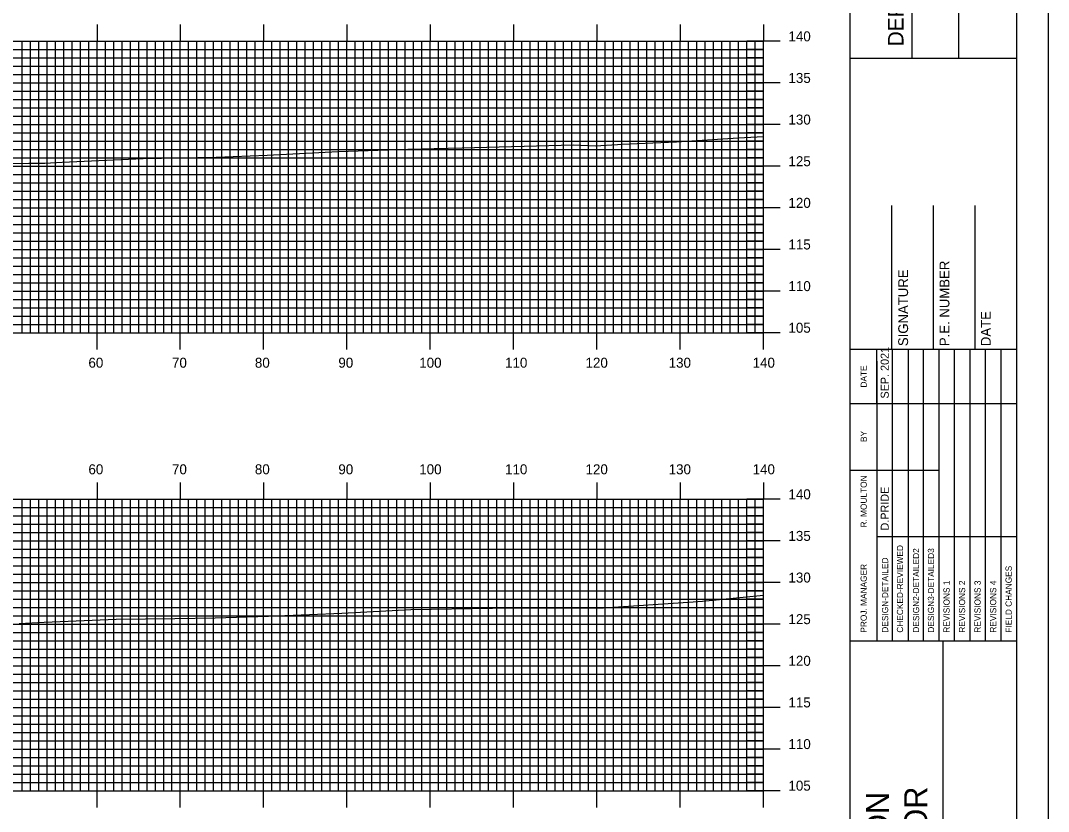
# Model space of a CAD drawing. Extents: x 852147 to 852490, y 364661 to 364881.
# Drawn here: x 852363.6 to 852487, y 364736.9 to 364831.9 of the extents above; entities that cross this region are included whole.
import ezdxf

# ---------------------------------------------------------------- set-up
doc = ezdxf.new("R2010")
doc.units = 0
for name, color, linetype in [('BORDER', 7, 'Continuous'), ('H_V ANNOTATION', 7, 'Continuous'), ('MAJOR', 7, 'Continuous'), ('MINOR', 7, 'Continuous'), ('PLOT BOUNDARY', 7, 'Continuous'), ('S_Roadway_Centerline', 7, 'Continuous')]:
    doc.layers.add(name, color=color, linetype=linetype)

msp = doc.modelspace()

# ---------------------------------------------------------------- linework, layer by layer
at = {"layer": 'BORDER'}
for p, q in [((852463.16, 364667.37), (852463.16, 364877.37)), ((852470.61, 364827.36), (852470.61, 364877.36)), ((852476.2, 364827.36), (852476.2, 364877.36)), ((852463.16, 364827.36), (852483.16, 364827.36)), ((852468.16, 364792.38), (852468.16, 364809.67)), ((852473.16, 364792.38), (852473.16, 364809.67)), ((852478.16, 364792.38), (852478.16, 364809.67)), ((852463.16, 364792.38), (852483.16, 364792.38)), ((852463.16, 364757.38), (852483.16, 364757.38)), ((852474.34, 364687.38), (852474.34, 364757.38))]:
    msp.add_line(p, q, dxfattribs=at)
msp.add_lwpolyline([(852163.16, 364667.37), (852483.16, 364667.37), (852483.16, 364877.37), (852163.16, 364877.37)], close=True, dxfattribs=at)
for points in [[(852466.38, 364785.88), (852466.38, 364792.38)], [(852468.25, 364757.38), (852468.25, 364792.38)], [(852470.11, 364792.38), (852470.11, 364757.38)], [(852471.98, 364757.38), (852471.98, 364792.38)], [(852473.84, 364757.38), (852473.84, 364792.38)], [(852475.7, 364757.38), (852475.7, 364792.38)], [(852477.57, 364757.38), (852477.57, 364792.38)], [(852479.43, 364757.38), (852479.43, 364792.38)], [(852481.29, 364757.38), (852481.29, 364792.38)], [(852466.39, 364757.38), (852466.39, 364790.96)], [(852463.16, 364785.88), (852483.16, 364785.88)], [(852463.16, 364777.88), (852466.39, 364777.88)], [(852466.38, 364777.88), (852473.84, 364777.88)], [(852466.38, 364769.88), (852483.16, 364769.88)]]:
    msp.add_lwpolyline(points, dxfattribs=at)
at = {"layer": 'MAJOR'}
for p, q in [((852372.76, 364831.37), (852372.76, 364829.37)), ((852382.76, 364831.37), (852382.76, 364829.37)), ((852392.76, 364831.37), (852392.76, 364829.37)), ((852402.76, 364831.37), (852402.76, 364829.37)), ((852412.76, 364831.37), (852412.76, 364829.37)), ((852422.76, 364831.37), (852422.76, 364829.37)), ((852432.76, 364831.37), (852432.76, 364829.37)), ((852442.76, 364831.37), (852442.76, 364829.37)), ((852452.76, 364831.37), (852452.76, 364829.37)), ((852172.76, 364829.37), (852452.76, 364829.37)), ((852172.76, 364829.37), (852452.76, 364829.37)), ((852372.76, 364794.37), (852372.76, 364829.37)), ((852382.76, 364794.37), (852382.76, 364829.37)), ((852392.76, 364794.37), (852392.76, 364829.37)), ((852402.76, 364794.37), (852402.76, 364829.37)), ((852412.76, 364794.37), (852412.76, 364829.37)), ((852422.76, 364794.37), (852422.76, 364829.37)), ((852432.76, 364794.37), (852432.76, 364829.37)), ((852442.76, 364794.37), (852442.76, 364829.37)), ((852454.76, 364829.37), (852450.75, 364829.37)), ((852452.76, 364794.37), (852452.76, 364829.37)), ((852452.76, 364794.37), (852452.76, 364829.37)), ((852172.76, 364824.37), (852452.76, 364824.37)), ((852454.76, 364824.37), (852450.75, 364824.37)), ((852172.76, 364819.37), (852452.76, 364819.37)), ((852454.76, 364819.37), (852450.75, 364819.37)), ((852172.76, 364814.37), (852452.76, 364814.37)), ((852454.76, 364814.37), (852450.75, 364814.37)), ((852172.76, 364809.37), (852452.76, 364809.37)), ((852454.76, 364809.37), (852450.75, 364809.37)), ((852172.76, 364804.37), (852452.76, 364804.37)), ((852454.76, 364804.37), (852450.75, 364804.37)), ((852172.76, 364799.37), (852452.76, 364799.37)), ((852454.76, 364799.37), (852450.75, 364799.37)), ((852172.76, 364794.37), (852452.76, 364794.37)), ((852172.76, 364794.37), (852452.76, 364794.37)), ((852372.76, 364792.37), (852372.76, 364794.37)), ((852382.76, 364792.37), (852382.76, 364794.37)), ((852392.76, 364792.37), (852392.76, 364794.37)), ((852402.76, 364792.37), (852402.76, 364794.37)), ((852412.76, 364792.37), (852412.76, 364794.37)), ((852422.76, 364792.37), (852422.76, 364794.37)), ((852432.76, 364792.37), (852432.76, 364794.37)), ((852442.76, 364792.37), (852442.76, 364794.37)), ((852454.76, 364794.37), (852450.75, 364794.37)), ((852452.76, 364792.37), (852452.76, 364794.37)), ((852372.76, 364776.37), (852372.76, 364774.37)), ((852382.76, 364776.37), (852382.76, 364774.37)), ((852392.76, 364776.37), (852392.76, 364774.37)), ((852402.76, 364776.37), (852402.76, 364774.37)), ((852412.76, 364776.37), (852412.76, 364774.37)), ((852422.76, 364776.37), (852422.76, 364774.37)), ((852432.76, 364776.37), (852432.76, 364774.37)), ((852442.76, 364776.37), (852442.76, 364774.37)), ((852452.76, 364776.37), (852452.76, 364774.37)), ((852172.76, 364774.37), (852452.76, 364774.37)), ((852172.76, 364774.37), (852452.76, 364774.37)), ((852372.76, 364739.37), (852372.76, 364774.37)), ((852382.76, 364739.37), (852382.76, 364774.37)), ((852392.76, 364739.37), (852392.76, 364774.37)), ((852402.76, 364739.37), (852402.76, 364774.37)), ((852412.76, 364739.37), (852412.76, 364774.37)), ((852422.76, 364739.37), (852422.76, 364774.37)), ((852432.76, 364739.37), (852432.76, 364774.37)), ((852442.76, 364739.37), (852442.76, 364774.37)), ((852454.76, 364774.37), (852450.75, 364774.37)), ((852452.76, 364739.37), (852452.76, 364774.37)), ((852452.76, 364739.37), (852452.76, 364774.37)), ((852172.76, 364769.37), (852452.76, 364769.37)), ((852454.76, 364769.37), (852450.75, 364769.37)), ((852172.76, 364764.37), (852452.76, 364764.37)), ((852454.76, 364764.37), (852450.75, 364764.37)), ((852172.76, 364759.37), (852452.76, 364759.37)), ((852454.76, 364759.37), (852450.75, 364759.37)), ((852172.76, 364754.37), (852452.76, 364754.37)), ((852454.76, 364754.37), (852450.75, 364754.37)), ((852172.76, 364749.37), (852452.76, 364749.37)), ((852454.76, 364749.37), (852450.75, 364749.37)), ((852172.76, 364744.37), (852452.76, 364744.37)), ((852454.76, 364744.37), (852450.75, 364744.37)), ((852172.76, 364739.37), (852452.76, 364739.37)), ((852172.76, 364739.37), (852452.76, 364739.37)), ((852372.76, 364737.37), (852372.76, 364739.37)), ((852382.76, 364737.37), (852382.76, 364739.37)), ((852392.76, 364737.37), (852392.76, 364739.37)), ((852402.76, 364737.37), (852402.76, 364739.37)), ((852412.76, 364737.37), (852412.76, 364739.37)), ((852422.76, 364737.37), (852422.76, 364739.37)), ((852432.76, 364737.37), (852432.76, 364739.37)), ((852442.76, 364737.37), (852442.76, 364739.37)), ((852454.76, 364739.37), (852450.75, 364739.37)), ((852452.76, 364737.37), (852452.76, 364739.37))]:
    msp.add_line(p, q, dxfattribs=at)
at = {"layer": 'MINOR'}
for p, q in [((852363.76, 364794.37), (852363.76, 364829.37)), ((852364.76, 364794.37), (852364.76, 364829.37)), ((852365.76, 364794.37), (852365.76, 364829.37)), ((852366.76, 364794.37), (852366.76, 364829.37)), ((852367.76, 364794.37), (852367.76, 364829.37)), ((852368.76, 364794.37), (852368.76, 364829.37)), ((852369.76, 364794.37), (852369.76, 364829.37)), ((852370.76, 364794.37), (852370.76, 364829.37)), ((852371.76, 364794.37), (852371.76, 364829.37)), ((852373.76, 364794.37), (852373.76, 364829.37)), ((852374.76, 364794.37), (852374.76, 364829.37)), ((852375.76, 364794.37), (852375.76, 364829.37)), ((852376.76, 364794.37), (852376.76, 364829.37)), ((852377.76, 364794.37), (852377.76, 364829.37)), ((852378.76, 364794.37), (852378.76, 364829.37)), ((852379.76, 364794.37), (852379.76, 364829.37)), ((852380.76, 364794.37), (852380.76, 364829.37)), ((852381.76, 364794.37), (852381.76, 364829.37)), ((852383.76, 364794.37), (852383.76, 364829.37)), ((852384.76, 364794.37), (852384.76, 364829.37)), ((852385.76, 364794.37), (852385.76, 364829.37)), ((852386.76, 364794.37), (852386.76, 364829.37)), ((852387.76, 364794.37), (852387.76, 364829.37)), ((852388.76, 364794.37), (852388.76, 364829.37)), ((852389.76, 364794.37), (852389.76, 364829.37)), ((852390.76, 364794.37), (852390.76, 364829.37)), ((852391.76, 364794.37), (852391.76, 364829.37)), ((852393.76, 364794.37), (852393.76, 364829.37)), ((852394.76, 364794.37), (852394.76, 364829.37)), ((852395.76, 364794.37), (852395.76, 364829.37)), ((852396.76, 364794.37), (852396.76, 364829.37)), ((852397.76, 364794.37), (852397.76, 364829.37)), ((852398.76, 364794.37), (852398.76, 364829.37)), ((852399.76, 364794.37), (852399.76, 364829.37)), ((852400.76, 364794.37), (852400.76, 364829.37)), ((852401.76, 364794.37), (852401.76, 364829.37)), ((852403.76, 364794.37), (852403.76, 364829.37)), ((852404.76, 364794.37), (852404.76, 364829.37)), ((852405.76, 364794.37), (852405.76, 364829.37)), ((852406.76, 364794.37), (852406.76, 364829.37)), ((852407.76, 364794.37), (852407.76, 364829.37)), ((852408.76, 364794.37), (852408.76, 364829.37)), ((852409.76, 364794.37), (852409.76, 364829.37)), ((852410.76, 364794.37), (852410.76, 364829.37)), ((852411.76, 364794.37), (852411.76, 364829.37)), ((852413.76, 364794.37), (852413.76, 364829.37)), ((852414.76, 364794.37), (852414.76, 364829.37)), ((852415.76, 364794.37), (852415.76, 364829.37)), ((852416.76, 364794.37), (852416.76, 364829.37)), ((852417.76, 364794.37), (852417.76, 364829.37)), ((852418.76, 364794.37), (852418.76, 364829.37)), ((852419.76, 364794.37), (852419.76, 364829.37)), ((852420.76, 364794.37), (852420.76, 364829.37)), ((852421.76, 364794.37), (852421.76, 364829.37)), ((852423.76, 364794.37), (852423.76, 364829.37)), ((852424.76, 364794.37), (852424.76, 364829.37)), ((852425.76, 364794.37), (852425.76, 364829.37)), ((852426.76, 364794.37), (852426.76, 364829.37)), ((852427.76, 364794.37), (852427.76, 364829.37)), ((852428.76, 364794.37), (852428.76, 364829.37)), ((852429.76, 364794.37), (852429.76, 364829.37)), ((852430.76, 364794.37), (852430.76, 364829.37)), ((852431.76, 364794.37), (852431.76, 364829.37)), ((852433.76, 364794.37), (852433.76, 364829.37)), ((852434.76, 364794.37), (852434.76, 364829.37)), ((852435.76, 364794.37), (852435.76, 364829.37)), ((852436.76, 364794.37), (852436.76, 364829.37)), ((852437.76, 364794.37), (852437.76, 364829.37)), ((852438.76, 364794.37), (852438.76, 364829.37)), ((852439.76, 364794.37), (852439.76, 364829.37)), ((852440.76, 364794.37), (852440.76, 364829.37)), ((852441.76, 364794.37), (852441.76, 364829.37)), ((852443.76, 364794.37), (852443.76, 364829.37)), ((852444.76, 364794.37), (852444.76, 364829.37)), ((852445.76, 364794.37), (852445.76, 364829.37)), ((852446.76, 364794.37), (852446.76, 364829.37)), ((852447.76, 364794.37), (852447.76, 364829.37)), ((852448.76, 364794.37), (852448.76, 364829.37)), ((852449.76, 364794.37), (852449.76, 364829.37)), ((852450.76, 364794.37), (852450.76, 364829.37)), ((852451.76, 364794.37), (852451.76, 364829.37)), ((852172.76, 364828.37), (852452.76, 364828.37)), ((852172.76, 364827.37), (852452.76, 364827.37)), ((852452.76, 364828.37), (852450.75, 364828.37)), ((852452.76, 364827.37), (852450.75, 364827.37)), ((852172.76, 364826.37), (852452.76, 364826.37)), ((852452.76, 364826.37), (852450.75, 364826.37)), ((852172.76, 364825.37), (852452.76, 364825.37)), ((852452.76, 364825.37), (852450.75, 364825.37)), ((852172.76, 364823.37), (852452.76, 364823.37)), ((852452.76, 364823.37), (852450.75, 364823.37)), ((852172.76, 364822.37), (852452.76, 364822.37)), ((852172.76, 364821.37), (852452.76, 364821.37)), ((852452.76, 364822.37), (852450.75, 364822.37)), ((852452.76, 364821.37), (852450.75, 364821.37)), ((852172.76, 364820.37), (852452.76, 364820.37)), ((852452.76, 364820.37), (852450.75, 364820.37)), ((852172.76, 364818.37), (852452.76, 364818.37)), ((852452.76, 364818.37), (852450.75, 364818.37)), ((852172.76, 364817.37), (852452.76, 364817.37)), ((852172.76, 364816.37), (852452.76, 364816.37)), ((852452.76, 364817.37), (852450.75, 364817.37)), ((852452.76, 364816.37), (852450.75, 364816.37)), ((852172.76, 364815.37), (852452.76, 364815.37)), ((852452.76, 364815.37), (852450.75, 364815.37)), ((852172.76, 364813.37), (852452.76, 364813.37)), ((852452.76, 364813.37), (852450.75, 364813.37)), ((852172.76, 364812.37), (852452.76, 364812.37)), ((852172.76, 364811.37), (852452.76, 364811.37)), ((852452.76, 364812.37), (852450.75, 364812.37)), ((852452.76, 364811.37), (852450.75, 364811.37)), ((852172.76, 364810.37), (852452.76, 364810.37)), ((852452.76, 364810.37), (852450.75, 364810.37)), ((852172.76, 364808.37), (852452.76, 364808.37)), ((852452.76, 364808.37), (852450.75, 364808.37)), ((852172.76, 364807.37), (852452.76, 364807.37)), ((852452.76, 364807.37), (852450.75, 364807.37)), ((852172.76, 364806.37), (852452.76, 364806.37)), ((852172.76, 364805.37), (852452.76, 364805.37)), ((852452.76, 364806.37), (852450.75, 364806.37)), ((852452.76, 364805.37), (852450.75, 364805.37)), ((852172.76, 364803.37), (852452.76, 364803.37)), ((852452.76, 364803.37), (852450.75, 364803.37)), ((852172.76, 364802.37), (852452.76, 364802.37)), ((852452.76, 364802.37), (852450.75, 364802.37)), ((852172.76, 364801.37), (852452.76, 364801.37)), ((852172.76, 364800.37), (852452.76, 364800.37)), ((852452.76, 364801.37), (852450.75, 364801.37)), ((852452.76, 364800.37), (852450.75, 364800.37)), ((852172.76, 364798.37), (852452.76, 364798.37)), ((852452.76, 364798.37), (852450.75, 364798.37)), ((852172.76, 364797.37), (852452.76, 364797.37)), ((852452.76, 364797.37), (852450.75, 364797.37)), ((852172.76, 364796.37), (852452.76, 364796.37)), ((852172.76, 364795.37), (852452.76, 364795.37)), ((852452.76, 364796.37), (852450.75, 364796.37)), ((852452.76, 364795.37), (852450.75, 364795.37)), ((852363.76, 364739.37), (852363.76, 364774.37)), ((852364.76, 364739.37), (852364.76, 364774.37)), ((852365.76, 364739.37), (852365.76, 364774.37)), ((852366.76, 364739.37), (852366.76, 364774.37)), ((852367.76, 364739.37), (852367.76, 364774.37)), ((852368.76, 364739.37), (852368.76, 364774.37)), ((852369.76, 364739.37), (852369.76, 364774.37)), ((852370.76, 364739.37), (852370.76, 364774.37)), ((852371.76, 364739.37), (852371.76, 364774.37)), ((852373.76, 364739.37), (852373.76, 364774.37)), ((852374.76, 364739.37), (852374.76, 364774.37)), ((852375.76, 364739.37), (852375.76, 364774.37)), ((852376.76, 364739.37), (852376.76, 364774.37)), ((852377.76, 364739.37), (852377.76, 364774.37)), ((852378.76, 364739.37), (852378.76, 364774.37)), ((852379.76, 364739.37), (852379.76, 364774.37)), ((852380.76, 364739.37), (852380.76, 364774.37)), ((852381.76, 364739.37), (852381.76, 364774.37)), ((852383.76, 364739.37), (852383.76, 364774.37)), ((852384.76, 364739.37), (852384.76, 364774.37)), ((852385.76, 364739.37), (852385.76, 364774.37)), ((852386.76, 364739.37), (852386.76, 364774.37)), ((852387.76, 364739.37), (852387.76, 364774.37)), ((852388.76, 364739.37), (852388.76, 364774.37)), ((852389.76, 364739.37), (852389.76, 364774.37)), ((852390.76, 364739.37), (852390.76, 364774.37)), ((852391.76, 364739.37), (852391.76, 364774.37)), ((852393.76, 364739.37), (852393.76, 364774.37)), ((852394.76, 364739.37), (852394.76, 364774.37)), ((852395.76, 364739.37), (852395.76, 364774.37)), ((852396.76, 364739.37), (852396.76, 364774.37)), ((852397.76, 364739.37), (852397.76, 364774.37)), ((852398.76, 364739.37), (852398.76, 364774.37)), ((852399.76, 364739.37), (852399.76, 364774.37)), ((852400.76, 364739.37), (852400.76, 364774.37)), ((852401.76, 364739.37), (852401.76, 364774.37)), ((852403.76, 364739.37), (852403.76, 364774.37)), ((852404.76, 364739.37), (852404.76, 364774.37)), ((852405.76, 364739.37), (852405.76, 364774.37)), ((852406.76, 364739.37), (852406.76, 364774.37)), ((852407.76, 364739.37), (852407.76, 364774.37)), ((852408.76, 364739.37), (852408.76, 364774.37)), ((852409.76, 364739.37), (852409.76, 364774.37)), ((852410.76, 364739.37), (852410.76, 364774.37)), ((852411.76, 364739.37), (852411.76, 364774.37)), ((852413.76, 364739.37), (852413.76, 364774.37)), ((852414.76, 364739.37), (852414.76, 364774.37)), ((852415.76, 364739.37), (852415.76, 364774.37)), ((852416.76, 364739.37), (852416.76, 364774.37)), ((852417.76, 364739.37), (852417.76, 364774.37)), ((852418.76, 364739.37), (852418.76, 364774.37)), ((852419.76, 364739.37), (852419.76, 364774.37)), ((852420.76, 364739.37), (852420.76, 364774.37)), ((852421.76, 364739.37), (852421.76, 364774.37)), ((852423.76, 364739.37), (852423.76, 364774.37)), ((852424.76, 364739.37), (852424.76, 364774.37)), ((852425.76, 364739.37), (852425.76, 364774.37)), ((852426.76, 364739.37), (852426.76, 364774.37)), ((852427.76, 364739.37), (852427.76, 364774.37)), ((852428.76, 364739.37), (852428.76, 364774.37)), ((852429.76, 364739.37), (852429.76, 364774.37)), ((852430.76, 364739.37), (852430.76, 364774.37)), ((852431.76, 364739.37), (852431.76, 364774.37)), ((852433.76, 364739.37), (852433.76, 364774.37)), ((852434.76, 364739.37), (852434.76, 364774.37)), ((852435.76, 364739.37), (852435.76, 364774.37)), ((852436.76, 364739.37), (852436.76, 364774.37)), ((852437.76, 364739.37), (852437.76, 364774.37)), ((852438.76, 364739.37), (852438.76, 364774.37)), ((852439.76, 364739.37), (852439.76, 364774.37)), ((852440.76, 364739.37), (852440.76, 364774.37)), ((852441.76, 364739.37), (852441.76, 364774.37)), ((852443.76, 364739.37), (852443.76, 364774.37)), ((852444.76, 364739.37), (852444.76, 364774.37)), ((852445.76, 364739.37), (852445.76, 364774.37)), ((852446.76, 364739.37), (852446.76, 364774.37)), ((852447.76, 364739.37), (852447.76, 364774.37)), ((852448.76, 364739.37), (852448.76, 364774.37)), ((852449.76, 364739.37), (852449.76, 364774.37)), ((852450.76, 364739.37), (852450.76, 364774.37)), ((852451.76, 364739.37), (852451.76, 364774.37)), ((852172.76, 364773.37), (852452.76, 364773.37)), ((852452.76, 364773.37), (852450.75, 364773.37)), ((852172.76, 364772.37), (852452.76, 364772.37)), ((852452.76, 364772.37), (852450.75, 364772.37)), ((852172.76, 364771.37), (852452.76, 364771.37)), ((852452.76, 364771.37), (852450.75, 364771.37)), ((852172.76, 364770.37), (852452.76, 364770.37)), ((852452.76, 364770.37), (852450.75, 364770.37)), ((852172.76, 364768.37), (852452.76, 364768.37)), ((852452.76, 364768.37), (852450.75, 364768.37)), ((852172.76, 364767.37), (852452.76, 364767.37)), ((852452.76, 364767.37), (852450.75, 364767.37)), ((852172.76, 364766.37), (852452.76, 364766.37)), ((852452.76, 364766.37), (852450.75, 364766.37)), ((852172.76, 364765.37), (852452.76, 364765.37)), ((852452.76, 364765.37), (852450.75, 364765.37)), ((852172.76, 364763.37), (852452.76, 364763.37)), ((852452.76, 364763.37), (852450.75, 364763.37)), ((852172.76, 364762.37), (852452.76, 364762.37)), ((852452.76, 364762.37), (852450.75, 364762.37)), ((852172.76, 364761.37), (852452.76, 364761.37)), ((852452.76, 364761.37), (852450.75, 364761.37)), ((852172.76, 364760.37), (852452.76, 364760.37)), ((852452.76, 364760.37), (852450.75, 364760.37)), ((852172.76, 364758.37), (852452.76, 364758.37)), ((852452.76, 364758.37), (852450.75, 364758.37)), ((852172.76, 364757.37), (852452.76, 364757.37)), ((852452.76, 364757.37), (852450.75, 364757.37)), ((852172.76, 364756.37), (852452.76, 364756.37)), ((852452.76, 364756.37), (852450.75, 364756.37)), ((852172.76, 364755.37), (852452.76, 364755.37)), ((852452.76, 364755.37), (852450.75, 364755.37)), ((852172.76, 364753.37), (852452.76, 364753.37)), ((852452.76, 364753.37), (852450.75, 364753.37)), ((852172.76, 364752.37), (852452.76, 364752.37)), ((852452.76, 364752.37), (852450.75, 364752.37)), ((852172.76, 364751.37), (852452.76, 364751.37)), ((852452.76, 364751.37), (852450.75, 364751.37)), ((852172.76, 364750.37), (852452.76, 364750.37)), ((852452.76, 364750.37), (852450.75, 364750.37)), ((852172.76, 364748.37), (852452.76, 364748.37)), ((852172.76, 364747.37), (852452.76, 364747.37)), ((852452.76, 364748.37), (852450.75, 364748.37)), ((852452.76, 364747.37), (852450.75, 364747.37)), ((852172.76, 364746.37), (852452.76, 364746.37)), ((852452.76, 364746.37), (852450.75, 364746.37)), ((852172.76, 364745.37), (852452.76, 364745.37)), ((852452.76, 364745.37), (852450.75, 364745.37)), ((852172.76, 364743.37), (852452.76, 364743.37)), ((852172.76, 364742.37), (852452.76, 364742.37)), ((852452.76, 364743.37), (852450.75, 364743.37)), ((852452.76, 364742.37), (852450.75, 364742.37)), ((852172.76, 364741.37), (852452.76, 364741.37)), ((852452.76, 364741.37), (852450.75, 364741.37)), ((852172.76, 364740.37), (852452.76, 364740.37)), ((852452.76, 364740.37), (852450.75, 364740.37))]:
    msp.add_line(p, q, dxfattribs=at)
at = {"layer": 'PLOT BOUNDARY'}
msp.add_lwpolyline([(852146.97, 364661.25), (852486.97, 364661.25), (852486.97, 364881.25), (852146.97, 364881.25)], close=True, dxfattribs=at)
at = {"layer": 'S_Roadway_Centerline'}
for points in [[(852354.84, 364814.54), (852364.58, 364814.72), (852366.51, 364814.73), (852368.58, 364814.85), (852378.28, 364815.3), (852387.08, 364815.45), (852393.18, 364815.69), (852401.69, 364816.15), (852410.05, 364816.4), (852413.24, 364816.5), (852416.6, 364816.57), (852429.95, 364816.94), (852432.54, 364816.82), (852435.22, 364816.97), (852435.7, 364817.02), (852440.43, 364817.22), (852442.32, 364817.31), (852449.72, 364817.78), (852452.76, 364817.95)], [(852363.41, 364759.46), (852366.4, 364759.6), (852375.06, 364759.96), (852382.11, 364760.06), (852386.93, 364760.12), (852393.35, 364760.35), (852398.28, 364760.53), (852402.13, 364760.7), (852410.43, 364761.13), (852420.25, 364761.3), (852422, 364761.35), (852423.61, 364761.34), (852423.79, 364761.34), (852429.44, 364761.32), (852433.36, 364761.32), (852433.55, 364761.34), (852444.33, 364762.07), (852445.45, 364762.12), (852452.76, 364762.85)]]:
    msp.add_lwpolyline(points, dxfattribs=at)

# ---------------------------------------------------------------- texts
at = {"layer": 'BORDER'}
for s, height, p in [('DEPARTMENT OF TRANSPORTATION', 1.8635, (852469.57, 364828.78)), ('P.E. NUMBER', 1.1811, (852475.08, 364792.76)), ('SIGNATURE', 1.181, (852470.12, 364792.76)), ('DATE', 1.181, (852480.04, 364792.76)), ('SEP. 2021', 0.969, (852467.8, 364786.47)), ('DATE', 0.743, (852465.16, 364787.79)), ('BY', 0.743, (852465.16, 364781.25)), ('R. MOULTON', 0.745, (852465.16, 364770.98)), ('D.PRIDE', 0.969, (852467.8, 364770.62)), ('CHECKED-REVIEWED', 0.7455, (852469.52, 364758.35)), ('DESIGN2-DETAILED2', 0.7455, (852471.45, 364758.35)), ('DESIGN3-DETAILED3', 0.7455, (852473.24, 364758.35)), ('DESIGN-DETAILED', 0.7455, (852467.73, 364758.35)), ('PROJ. MANAGER', 0.7455, (852465.16, 364758.35)), ('FIELD CHANGES', 0.7455, (852482.56, 364758.35)), ('REVISIONS 1', 0.7455, (852475.11, 364758.35)), ('REVISIONS 2', 0.7455, (852476.97, 364758.35)), ('REVISIONS 3', 0.7455, (852478.83, 364758.35)), ('REVISIONS 4', 0.7455, (852480.7, 364758.35)), ('BREWER TO EDDINGTON', 2.7557, (852467.83, 364693.78)), ('I-395/ROUTE 9 CONNECTOR', 2.7557, (852472.42, 364689.7))]:
    msp.add_text(s, height=height, rotation=90, dxfattribs=at).set_placement(p)
at = {"layer": 'H_V ANNOTATION'}
for s, p in [('140', (852455.76, 364829.37)), ('135', (852455.76, 364824.37)), ('130', (852455.76, 364819.37)), ('125', (852455.76, 364814.37)), ('120', (852455.76, 364809.37)), ('115', (852455.76, 364804.37)), ('110', (852455.76, 364799.37)), ('105', (852455.76, 364794.37)), ('60', (852371.73, 364790.17)), ('70', (852381.76, 364790.17)), ('80', (852391.71, 364790.17)), ('90', (852401.73, 364790.17)), ('100', (852411.44, 364790.17)), ('110', (852421.74, 364790.17)), ('120', (852431.4, 364790.17)), ('130', (852441.38, 364790.17)), ('140', (852451.46, 364790.17)), ('60', (852371.73, 364777.37)), ('70', (852381.76, 364777.37)), ('80', (852391.71, 364777.37)), ('90', (852401.73, 364777.37)), ('100', (852411.44, 364777.37)), ('110', (852421.74, 364777.37)), ('120', (852431.4, 364777.37)), ('130', (852441.38, 364777.37)), ('140', (852451.46, 364777.37)), ('140', (852455.76, 364774.37)), ('135', (852455.76, 364769.37)), ('130', (852455.76, 364764.37)), ('125', (852455.76, 364759.37)), ('120', (852455.76, 364754.37)), ('115', (852455.76, 364749.37)), ('110', (852455.76, 364744.37)), ('105', (852455.76, 364739.37))]:
    msp.add_text(s, height=1.2, dxfattribs=at).set_placement(p)

doc.saveas('drawing.dxf')
